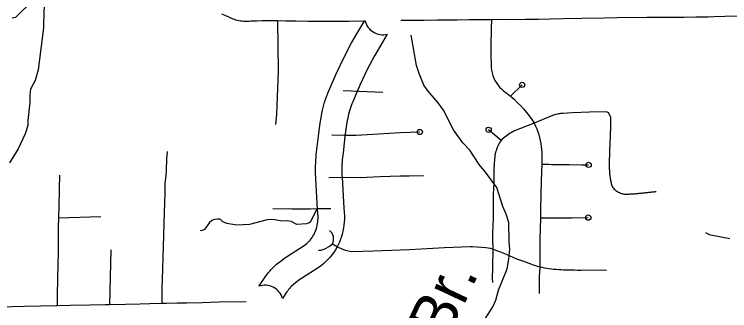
# Model space of a CAD drawing. Extents: x -19 to 366, y -4 to 359.
# Drawn here: x 152.307 to 153.594, y 181.952 to 182.486 of the extents above; entities that cross this region are included whole.
import ezdxf

# ---------------------------------------------------------------- set-up
doc = ezdxf.new("R2010")
doc.units = 0
for name, color, linetype in [('Level 10', 7, 'Continuous'), ('Level 31', 7, 'Continuous'), ('Level 32', 7, 'Continuous'), ('Level 35', 7, 'Continuous'), ('Level 60', 7, 'Continuous')]:
    doc.layers.add(name, color=color, linetype=linetype)

msp = doc.modelspace()

# ---------------------------------------------------------------- linework, layer by layer
at = {"layer": 'Level 10'}
for p, q in [((152.9205, 182.3384), (152.9206, 182.3384)), ((152.9021, 182.2654), (152.9021, 182.2657)), ((152.897, 182.1925), (152.897, 182.1924)), ((152.897, 182.1924), (152.9003, 182.1368)), ((152.9003, 182.1368), (152.9003, 182.1368)), ((152.897, 182.0897), (152.897, 182.0895)), ((152.8715, 182.044), (152.871, 182.0435))]:
    msp.add_line(p, q, dxfattribs=at)
for points in [[(152.8771, 182.3572), (152.8864, 182.3786), (152.8998, 182.4073), (152.9141, 182.4341), (152.9291, 182.4595), (152.938, 182.4746)], [(152.9783, 182.4497), (152.9698, 182.4354), (152.9554, 182.411), (152.9422, 182.3862), (152.9296, 182.3591), (152.9205, 182.3384)], [(152.8551, 182.2715), (152.8575, 182.2898), (152.8597, 182.3028), (152.8606, 182.3077), (152.8617, 182.3128), (152.8629, 182.3178), (152.8655, 182.3272), (152.8671, 182.3321), (152.8687, 182.3368), (152.8705, 182.3416), (152.8724, 182.3463), (152.8771, 182.3572)], [(152.9206, 182.3384), (152.9161, 182.3282), (152.9147, 182.3246), (152.9133, 182.3209), (152.9121, 182.3172), (152.9109, 182.3135), (152.9087, 182.3057), (152.9078, 182.3021), (152.907, 182.2984), (152.9063, 182.2946), (152.9044, 182.2829), (152.9021, 182.2654)], [(152.8497, 182.1895), (152.8495, 182.1926), (152.8493, 182.1977), (152.8492, 182.2028), (152.8492, 182.2078), (152.8493, 182.2128), (152.8495, 182.2177), (152.8498, 182.2226), (152.8501, 182.2276), (152.8506, 182.2326), (152.8511, 182.2375), (152.8517, 182.242), (152.8551, 182.2712)], [(152.9021, 182.2657), (152.8987, 182.2364), (152.8982, 182.2319), (152.8977, 182.2278), (152.8973, 182.2237), (152.897, 182.2197), (152.8968, 182.2155), (152.8966, 182.2113), (152.8965, 182.2073), (152.8965, 182.2032), (152.8966, 182.1992), (152.8968, 182.1952), (152.897, 182.1925)], [(152.853, 182.134), (152.8497, 182.1896)], [(152.9003, 182.1368), (152.9011, 182.1221), (152.9011, 182.1167), (152.9008, 182.1114), (152.9003, 182.1062), (152.8995, 182.1009), (152.8985, 182.0958), (152.8974, 182.0908), (152.897, 182.0897)], [(152.8514, 182.1024), (152.8515, 182.1025), (152.8522, 182.1058), (152.8528, 182.1088), (152.8532, 182.1119), (152.8536, 182.1151), (152.8537, 182.1182), (152.8538, 182.1211), (152.853, 182.1339)], [(152.8372, 182.0766), (152.8373, 182.0767), (152.8394, 182.0791), (152.8413, 182.0814), (152.843, 182.0836), (152.8444, 182.0859), (152.846, 182.0886), (152.8474, 182.0913), (152.8486, 182.094), (152.8497, 182.0968), (152.8507, 182.0997), (152.8515, 182.1027)], [(152.897, 182.0895), (152.8959, 182.0856), (152.8942, 182.0806), (152.8922, 182.0756), (152.89, 182.0706), (152.8876, 182.066), (152.885, 182.0615), (152.882, 182.0568), (152.8788, 182.0524), (152.8754, 182.0483), (152.8721, 182.0446), (152.8715, 182.044)], [(152.747, 181.9959), (152.7475, 181.9965), (152.7567, 182.01), (152.7589, 182.0133), (152.7614, 182.0166), (152.764, 182.02), (152.7668, 182.0233), (152.7696, 182.0264), (152.7725, 182.0294), (152.7756, 182.0324), (152.7792, 182.0357), (152.785, 182.0402), (152.7933, 182.0463), (152.7972, 182.0491), (152.8287, 182.0694), (152.831, 182.0711), (152.8333, 182.073), (152.8355, 182.0749), (152.8377, 182.0771)], [(152.871, 182.0435), (152.868, 182.0404), (152.8641, 182.037), (152.8599, 182.0336), (152.8555, 182.0304), (152.8239, 182.01), (152.8212, 182.0081), (152.8134, 182.0023), (152.8096, 181.9994), (152.8081, 181.998), (152.8062, 181.9961), (152.8043, 181.9942), (152.8025, 181.9921), (152.8007, 181.9901), (152.7991, 181.988), (152.7975, 181.9858), (152.7958, 181.9833), (152.7895, 181.9741)]]:
    msp.add_lwpolyline(points, dxfattribs=at)
for centre, radius, start, end in [((152.9704, 182.4819), 0.0332, 192.6881, 283.8535), ((152.7584, 181.9658), 0.0322, 15.0877, 110.7349)]:
    msp.add_arc(centre, radius, start, end, dxfattribs=at)
at = {"layer": 'Level 31'}
for points in [[(152.7807, 182.4735), (152.7739, 182.4736), (152.7636, 182.4737), (152.7533, 182.4736), (152.743, 182.4734), (152.7327, 182.4732), (152.73, 182.4728), (152.7274, 182.4726), (152.7247, 182.4725), (152.722, 182.4726), (152.7193, 182.4727), (152.7166, 182.4729), (152.714, 182.4733), (152.7113, 182.4738), (152.7087, 182.4744), (152.7061, 182.4751), (152.7036, 182.4759), (152.701, 182.4768), (152.6866, 182.4832), (152.6838, 182.4845), (152.6809, 182.4856)], [(153.6335, 182.4825), (153.6095, 182.4819), (153.5854, 182.4814), (153.5666, 182.4809)], [(152.7807, 182.4735), (152.782, 182.3833), (152.7789, 182.3059), (152.7771, 182.2872)], [(152.9384, 182.4732), (152.9088, 182.4725), (152.8958, 182.4726), (152.8365, 182.4727), (152.8139, 182.4731), (152.796, 182.4731), (152.7807, 182.4735)], [(153.128, 182.4755), (153.125, 182.4755), (153.1039, 182.4751), (153.084, 182.4751), (153.0686, 182.4747), (153.0446, 182.4746), (153.0227, 182.4745), (153.0026, 182.4744)], [(153.1659, 182.4757), (153.1467, 182.4755), (153.128, 182.4755)], [(153.1659, 182.4757), (153.1651, 182.4605), (153.1646, 182.4283), (153.1644, 182.4153), (153.165, 182.3895), (153.1657, 182.3847), (153.1668, 182.3799), (153.1682, 182.3753), (153.1699, 182.3708), (153.172, 182.3664), (153.1745, 182.3623), (153.1773, 182.3583), (153.1803, 182.3546), (153.1837, 182.3511), (153.1873, 182.3479), (153.1938, 182.343), (153.2, 182.3381)], [(153.5666, 182.4809), (153.5553, 182.4806), (153.5335, 182.4803), (153.5116, 182.4799), (153.4928, 182.4799), (153.4642, 182.4796), (153.4452, 182.4796), (153.3917, 182.479), (153.3683, 182.4786), (153.328, 182.4779), (153.2954, 182.4775), (153.2719, 182.4769), (153.2501, 182.4763), (153.2267, 182.4761), (153.2102, 182.4758), (153.1851, 182.4759), (153.1659, 182.4757)], [(153.221, 182.3585), (153.2, 182.3381)], [(153.2, 182.3381), (153.2001, 182.3379), (153.2063, 182.3326), (153.2122, 182.327), (153.2178, 182.3212), (153.2233, 182.3153), (153.2286, 182.309), (153.2336, 182.3027), (153.2383, 182.2961), (153.2428, 182.2894)], [(153.3734, 182.3098), (153.3419, 182.3096), (153.3116, 182.308), (153.2933, 182.3072), (153.2897, 182.3068), (153.2879, 182.3066), (153.286, 182.3063), (153.2843, 182.3059), (153.2807, 182.305), (153.279, 182.3045), (153.2772, 182.304), (153.2754, 182.3034), (153.2428, 182.2894)], [(153.3734, 182.3098), (153.3759, 182.3085), (153.3767, 182.3071), (153.3777, 182.3054), (153.3787, 182.3037), (153.3794, 182.302), (153.3798, 182.3002), (153.3798, 182.2983), (153.3798, 182.2964), (153.3798, 182.2945), (153.3798, 182.2926), (153.3798, 182.2908), (153.3798, 182.2889), (153.3798, 182.287), (153.3798, 182.2851), (153.3797, 182.2832), (153.3797, 182.2813), (153.3797, 182.2794), (153.3796, 182.2775), (153.3796, 182.2756), (153.3795, 182.2737), (153.3794, 182.2718), (153.3794, 182.2699), (153.3793, 182.268), (153.3792, 182.2662), (153.3791, 182.2643), (153.3791, 182.2624), (153.379, 182.2605), (153.3789, 182.2586), (153.3788, 182.2567), (153.3787, 182.2548), (153.3786, 182.2529), (153.3786, 182.251), (153.3785, 182.2491), (153.3784, 182.2472), (153.3783, 182.2453), (153.3782, 182.2434), (153.3782, 182.2415), (153.3781, 182.2396), (153.378, 182.2377), (153.378, 182.2358), (153.3779, 182.2339), (153.3779, 182.232), (153.3778, 182.2301), (153.3778, 182.2282), (153.3777, 182.2263), (153.3777, 182.2244), (153.3776, 182.2225), (153.3776, 182.2206), (153.3776, 182.2187), (153.3776, 182.2168), (153.3776, 182.2149), (153.3776, 182.213), (153.3776, 182.2111), (153.3777, 182.2092), (153.3777, 182.2073), (153.3778, 182.2054), (153.3778, 182.2035), (153.378, 182.2016), (153.3781, 182.1997), (153.3783, 182.1978), (153.3785, 182.1959), (153.3787, 182.1939), (153.379, 182.192), (153.3793, 182.1902), (153.3796, 182.1883), (153.38, 182.1864), (153.3804, 182.1846), (153.3808, 182.1827), (153.3813, 182.1809), (153.3818, 182.1791), (153.3824, 182.1774), (153.3831, 182.1757), (153.3841, 182.174), (153.3852, 182.1724), (153.3866, 182.1709), (153.388, 182.1696), (153.3895, 182.1684), (153.391, 182.1673), (153.3926, 182.1664), (153.3943, 182.1654), (153.3961, 182.1646), (153.3979, 182.1638), (153.3997, 182.1632), (153.4016, 182.1626), (153.4034, 182.1622), (153.4053, 182.162), (153.4072, 182.162), (153.4091, 182.162), (153.4109, 182.162), (153.4128, 182.162), (153.4147, 182.1621), (153.4165, 182.1622), (153.4184, 182.1623), (153.4203, 182.1624), (153.4222, 182.1625), (153.4241, 182.1626), (153.426, 182.1628), (153.4279, 182.1629), (153.4298, 182.1631)], [(153.2428, 182.2894), (153.2073, 182.2757), (153.2046, 182.2744), (153.202, 182.273), (153.1994, 182.2715), (153.1968, 182.2699), (153.1943, 182.2682), (153.1919, 182.2664), (153.1896, 182.2646), (153.1873, 182.2626), (153.1851, 182.2606), (153.183, 182.2585)], [(153.2428, 182.2894), (153.2451, 182.2844), (153.2473, 182.2793), (153.2492, 182.2742), (153.2509, 182.2689), (153.2524, 182.2637), (153.2536, 182.2583), (153.2546, 182.2529), (153.2554, 182.2475), (153.2559, 182.242), (153.2562, 182.2365), (153.2566, 182.2158)], [(153.183, 182.2585), (153.1606, 182.2776)], [(152.8786, 182.2685), (152.9003, 182.268), (152.9224, 182.2682), (153.0021, 182.273), (153.0368, 182.2737)], [(153.183, 182.2585), (153.1813, 182.2561), (153.1798, 182.2535), (153.1784, 182.2509), (153.1771, 182.2482), (153.176, 182.2455), (153.1749, 182.2428), (153.174, 182.24), (153.1731, 182.2372), (153.1724, 182.2343), (153.1718, 182.2314), (153.171, 182.2221), (153.1707, 182.219), (153.1706, 182.2159), (153.1703, 182.2129), (153.1702, 182.2098), (153.17, 182.2067), (153.1698, 182.2005), (153.1699, 182.1828), (153.169, 182.1611), (153.1686, 182.1411), (153.1685, 182.1211), (153.1683, 182.1043), (153.1678, 182.0935), (153.1677, 182.0799), (153.1679, 182.063)], [(152.5822, 182.2384), (152.581, 182.2256), (152.5802, 182.2042), (152.5801, 182.195), (152.5781, 182.1815), (152.5781, 182.1631), (152.5776, 182.1466), (152.5764, 182.109), (152.5755, 182.0878), (152.5751, 182.0668), (152.5745, 182.0477), (152.5736, 182.0275), (152.5733, 182.0088), (152.5728, 181.9926), (152.5726, 181.9648)], [(153.2566, 182.2158), (153.2552, 182.1858), (153.2545, 182.1614), (153.2541, 182.1356), (153.2537, 182.119)], [(153.2566, 182.2158), (153.2691, 182.2155), (153.2742, 182.2154), (153.3054, 182.215), (153.3281, 182.2145), (153.3405, 182.2145)], [(152.3887, 182.1961), (152.3878, 182.1715), (152.3872, 182.1378), (152.3869, 182.1233), (152.3867, 182.1191)], [(153.0434, 182.1952), (153.043, 182.195), (153.0176, 182.194), (153.0012, 182.1943), (152.9655, 182.1932), (152.9295, 182.1914), (152.9061, 182.1918), (152.8733, 182.191)], [(153.4298, 182.1631), (153.4316, 182.1633), (153.4335, 182.1635), (153.4354, 182.1637), (153.4373, 182.1639), (153.4392, 182.1641), (153.4411, 182.1643), (153.443, 182.1645), (153.4449, 182.1647), (153.4468, 182.1649), (153.4487, 182.1652), (153.4506, 182.1654), (153.4525, 182.1656), (153.4544, 182.1658), (153.4562, 182.166), (153.4582, 182.1662), (153.46, 182.1664), (153.4619, 182.1666)], [(152.8515, 182.1351), (152.8394, 182.1349), (152.8064, 182.1346), (152.7723, 182.1356)], [(152.8766, 182.1354), (152.8515, 182.1351)], [(152.3867, 182.1191), (152.386, 182.1016), (152.3862, 182.0802), (152.3859, 182.0558), (152.3857, 182.0362), (152.3849, 182.0091), (152.3845, 181.9804), (152.3843, 181.9608)], [(152.3867, 182.1191), (152.4628, 182.1213)], [(153.2537, 182.119), (153.2534, 182.0996), (153.253, 182.0815), (153.2527, 182.0583), (153.2529, 182.0305)], [(153.2537, 182.119), (153.2822, 182.1191), (153.3099, 182.1191), (153.3399, 182.1196)], [(152.88, 182.0715), (152.8813, 182.0778), (152.8818, 182.0856), (152.8792, 182.0918), (152.8742, 182.0961)], [(153.5947, 182.0816), (153.5603, 182.0882), (153.5555, 182.0899), (153.5513, 182.0921)], [(152.88, 182.0715), (152.8745, 182.0673), (152.8653, 182.063), (152.8589, 182.0604), (152.8544, 182.0603)], [(153.1679, 182.063), (153.1639, 182.0637), (153.1558, 182.0649), (153.1477, 182.0658), (153.1395, 182.0664), (153.1314, 182.0668), (153.1273, 182.0669), (153.0812, 182.0652), (153.0185, 182.0614), (152.9535, 182.0594), (152.9131, 182.058), (152.9032, 182.0603), (152.8885, 182.0663), (152.88, 182.0715)], [(152.4808, 182.0613), (152.4786, 181.9626)], [(153.1679, 182.063), (153.1673, 182.0289), (153.1672, 182.0104), (153.1675, 182.003)], [(153.2529, 182.0305), (153.2415, 182.0341), (153.226, 182.0399), (153.2115, 182.0449), (153.193, 182.0531), (153.1805, 182.0581), (153.1754, 182.06), (153.1679, 182.063)], [(153.2529, 182.0305), (153.2517, 182.0129), (153.2517, 181.9994), (153.2515, 181.9829)], [(153.3724, 182.0246), (153.3649, 182.0248), (153.3271, 182.0244), (153.3239, 182.0245), (153.3207, 182.0245), (153.3143, 182.0247), (153.3111, 182.0248), (153.3015, 182.025), (153.2983, 182.0251), (153.2951, 182.0252), (153.2909, 182.0254), (153.2866, 182.0256), (153.2823, 182.0259), (153.2781, 182.0264), (153.2739, 182.0269), (153.2697, 182.0274), (153.2655, 182.0281), (153.2612, 182.0288), (153.2571, 182.0296), (153.2529, 182.0305)], [(152.7246, 181.968), (152.675, 181.9672), (152.6455, 181.9664), (152.6178, 181.9658), (152.6003, 181.9654), (152.581, 181.9651), (152.5726, 181.9648)], [(152.3843, 181.9608), (152.3819, 181.9608), (152.3552, 181.9602), (152.3257, 181.9597), (152.3036, 181.959), (152.279, 181.9583), (152.2473, 181.9578), (152.2373, 181.9574), (152.2273, 181.9571), (152.2173, 181.9569), (152.2073, 181.9568), (152.1665, 181.9564), (152.1393, 181.9561), (152.1094, 181.9559), (152.0974, 181.9558)], [(152.4786, 181.9626), (152.4707, 181.9625), (152.4431, 181.962), (152.4078, 181.9612), (152.3843, 181.9608)], [(152.5726, 181.9648), (152.5512, 181.9642), (152.5334, 181.9638), (152.5071, 181.9634), (152.4786, 181.9626)]]:
    msp.add_lwpolyline(points, dxfattribs=at)
for centre in [(153.221, 182.3585), (153.0368, 182.2737), (153.1606, 182.2776), (153.3405, 182.2145), (153.3399, 182.1196)]:
    msp.add_circle(centre, 0.00473, dxfattribs=at)
at = {"layer": 'Level 32'}
msp.add_line((152.899, 182.3483), (152.97, 182.3453), dxfattribs=at)
msp.add_lwpolyline([(152.8515, 182.1351), (152.8399, 182.1121), (152.8377, 182.11), (152.833, 182.1082), (152.8155, 182.1074), (152.8055, 182.1128), (152.799, 182.1137), (152.7888, 182.1131), (152.7758, 182.1155), (152.7693, 182.1162), (152.7619, 182.1157), (152.7508, 182.1123), (152.7301, 182.1071), (152.7075, 182.1062), (152.6897, 182.1087), (152.6825, 182.1122), (152.6779, 182.1166), (152.6728, 182.117), (152.6677, 182.1163), (152.6627, 182.1141), (152.6586, 182.1106), (152.6494, 182.0982), (152.6455, 182.0964), (152.6418, 182.0955)], dxfattribs=at)
at = {"layer": 'Level 35'}
for points in [[(152.4765, 182.725), (152.4744, 182.7166), (152.465, 182.7016), (152.4627, 182.696), (152.4576, 182.6755), (152.4518, 182.6598), (152.4474, 182.6531), (152.4237, 182.6264), (152.3906, 182.5969), (152.3754, 182.5794), (152.369, 182.5645), (152.3652, 182.5372), (152.3606, 182.4926), (152.3595, 182.4614), (152.35, 182.3855), (152.3448, 182.3666), (152.3366, 182.3505), (152.3351, 182.3412), (152.3352, 182.327), (152.3317, 182.2943), (152.3318, 182.2855), (152.3266, 182.2704), (152.3143, 182.2436), (152.2985, 182.2183)], [(152.3409, 182.5106), (152.3093, 182.4798)], [(152.3093, 182.4798), (152.3035, 182.4788)], [(153.1503, 181.9307), (153.1683, 181.9591), (153.1734, 181.9708), (153.1783, 181.9888), (153.1939, 182.0272), (153.197, 182.0445), (153.1989, 182.0626), (153.1975, 182.0764), (153.1972, 182.1109), (153.1922, 182.1257), (153.1862, 182.1396), (153.1751, 182.1739), (153.1551, 182.2016), (153.1437, 182.2151), (153.1267, 182.2407), (153.1143, 182.2542), (153.0974, 182.2778), (153.0793, 182.3129), (153.0698, 182.3262), (153.0518, 182.3469), (153.044, 182.358), (153.0354, 182.3792), (153.031, 182.3936), (153.021, 182.4482)]]:
    msp.add_lwpolyline(points, dxfattribs=at)
at = {"layer": 'Level 60'}
for points in [[(154.1159, 1.8709), (153.9063, 10.4874), (153.696, 19.1041), (153.485, 27.7209), (153.2733, 36.3378), (153.0608, 44.9549), (152.8476, 53.5721), (152.6337, 62.1894), (152.419, 70.8069), (152.2036, 79.4245), (151.9875, 88.0422), (151.7707, 96.6601), (151.5531, 105.2782), (151.3348, 113.8963), (151.1158, 122.5147), (150.8961, 131.1331), (150.6757, 139.7517), (150.4545, 148.3704), (150.2326, 156.9893), (150.0101, 165.6083), (149.7867, 174.2275), (149.5627, 182.8468), (149.338, 191.4662), (149.1125, 200.0858), (148.8864, 208.7055), (148.6595, 217.3254), (148.4319, 225.9454), (148.2037, 234.5655), (147.9747, 243.1858), (147.745, 251.8063), (147.5146, 260.4269), (147.2835, 269.0476), (147.0517, 277.6685), (146.8191, 286.2895), (146.5859, 294.9106), (146.352, 303.5319), (146.1174, 312.1534), (145.8821, 320.775), (145.6461, 329.3967), (145.4094, 338.0186), (145.172, 346.6406)], [(0, 180.8999), (7.1228, 180.9044), (14.2457, 180.9176), (21.3685, 180.9397), (28.4912, 180.9706), (35.614, 181.0103), (42.7366, 181.0589), (49.8592, 181.1163), (56.9818, 181.1825), (64.1042, 181.2575), (71.2266, 181.3414), (78.3488, 181.4341), (85.4709, 181.5357), (92.5929, 181.646), (99.7147, 181.7652), (106.8364, 181.8933), (113.9579, 182.0301), (121.0793, 182.1758), (128.2005, 182.3303), (135.3214, 182.4936), (142.4422, 182.6658), (149.5627, 182.8468), (156.683, 183.0366), (163.8031, 183.2352), (170.9229, 183.4427), (178.0425, 183.659), (185.1617, 183.8841), (192.2807, 184.1181), (199.3994, 184.3608), (206.5178, 184.6124), (213.6359, 184.8728), (220.7537, 185.1421), (227.8711, 185.4201), (234.9881, 185.707), (242.1048, 186.0027), (249.2212, 186.3073), (256.3371, 186.6206), (263.4526, 186.9428), (270.5678, 187.2738), (277.6825, 187.6136), (284.7968, 187.9622), (291.9107, 188.3197), (299.0241, 188.6859), (306.1371, 189.061), (313.2495, 189.4449), (320.3615, 189.8377), (327.4731, 190.2392), (334.5841, 190.6495), (341.6946, 191.0687)], [(0, 172.2839), (7.1335, 172.2883), (14.267, 172.3015), (21.4005, 172.3236), (28.5339, 172.3544), (35.6673, 172.3941), (42.8006, 172.4426), (49.9339, 172.4999), (57.0671, 172.566), (64.2002, 172.6409), (71.3332, 172.7246), (78.4661, 172.8172), (85.5989, 172.9186), (92.7315, 173.0287), (99.8641, 173.1477), (106.9964, 173.2755), (114.1286, 173.4122), (121.2606, 173.5576), (128.3925, 173.7119), (135.5241, 173.8749), (142.6555, 174.0468), (149.7867, 174.2275), (156.9177, 174.417), (164.0485, 174.6153), (171.179, 174.8224), (178.3092, 175.0383), (185.4392, 175.2631), (192.5688, 175.4966), (199.6982, 175.739), (206.8273, 175.9902), (213.9561, 176.2502), (221.0845, 176.5189), (228.2126, 176.7965), (235.3404, 177.083), (242.4677, 177.3782), (249.5948, 177.6822), (256.7214, 177.995), (263.8476, 178.3167), (270.9735, 178.6471), (278.0989, 178.9863), (285.2239, 179.3344), (292.3485, 179.6912), (299.4726, 180.0569), (306.5963, 180.4314), (313.7195, 180.8146), (320.8422, 181.2067), (327.9644, 181.6076), (335.0862, 182.0172), (342.2074, 182.4357)]]:
    msp.add_spline(points, degree=3, dxfattribs=at)

# ---------------------------------------------------------------- texts
at = {"layer": 'Level 35'}
msp.add_text('Br.', height=0.08, rotation=64.9022, dxfattribs=at).set_placement((153.0853, 181.8952))

doc.saveas('drawing.dxf')
